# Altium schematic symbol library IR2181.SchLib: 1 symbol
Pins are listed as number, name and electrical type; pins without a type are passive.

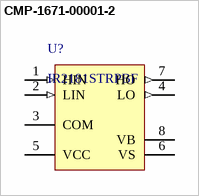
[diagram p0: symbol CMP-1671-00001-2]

## CMP-1671-00001-2
designator U?, comment IR2181STRPBF
IC DRIVER HIGH/LOW SIDE 8SOIC; Manufacturer: International Rectifier
footprint INTR-SOIC-8_V
pins: 1 HIN (in), 2 LIN (in), 3 COM, 4 LO (out), 5 VCC (power), 6 VS (power), 7 HO (out), 8 VB (power)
